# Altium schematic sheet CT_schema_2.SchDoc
size 551 x 486 mm
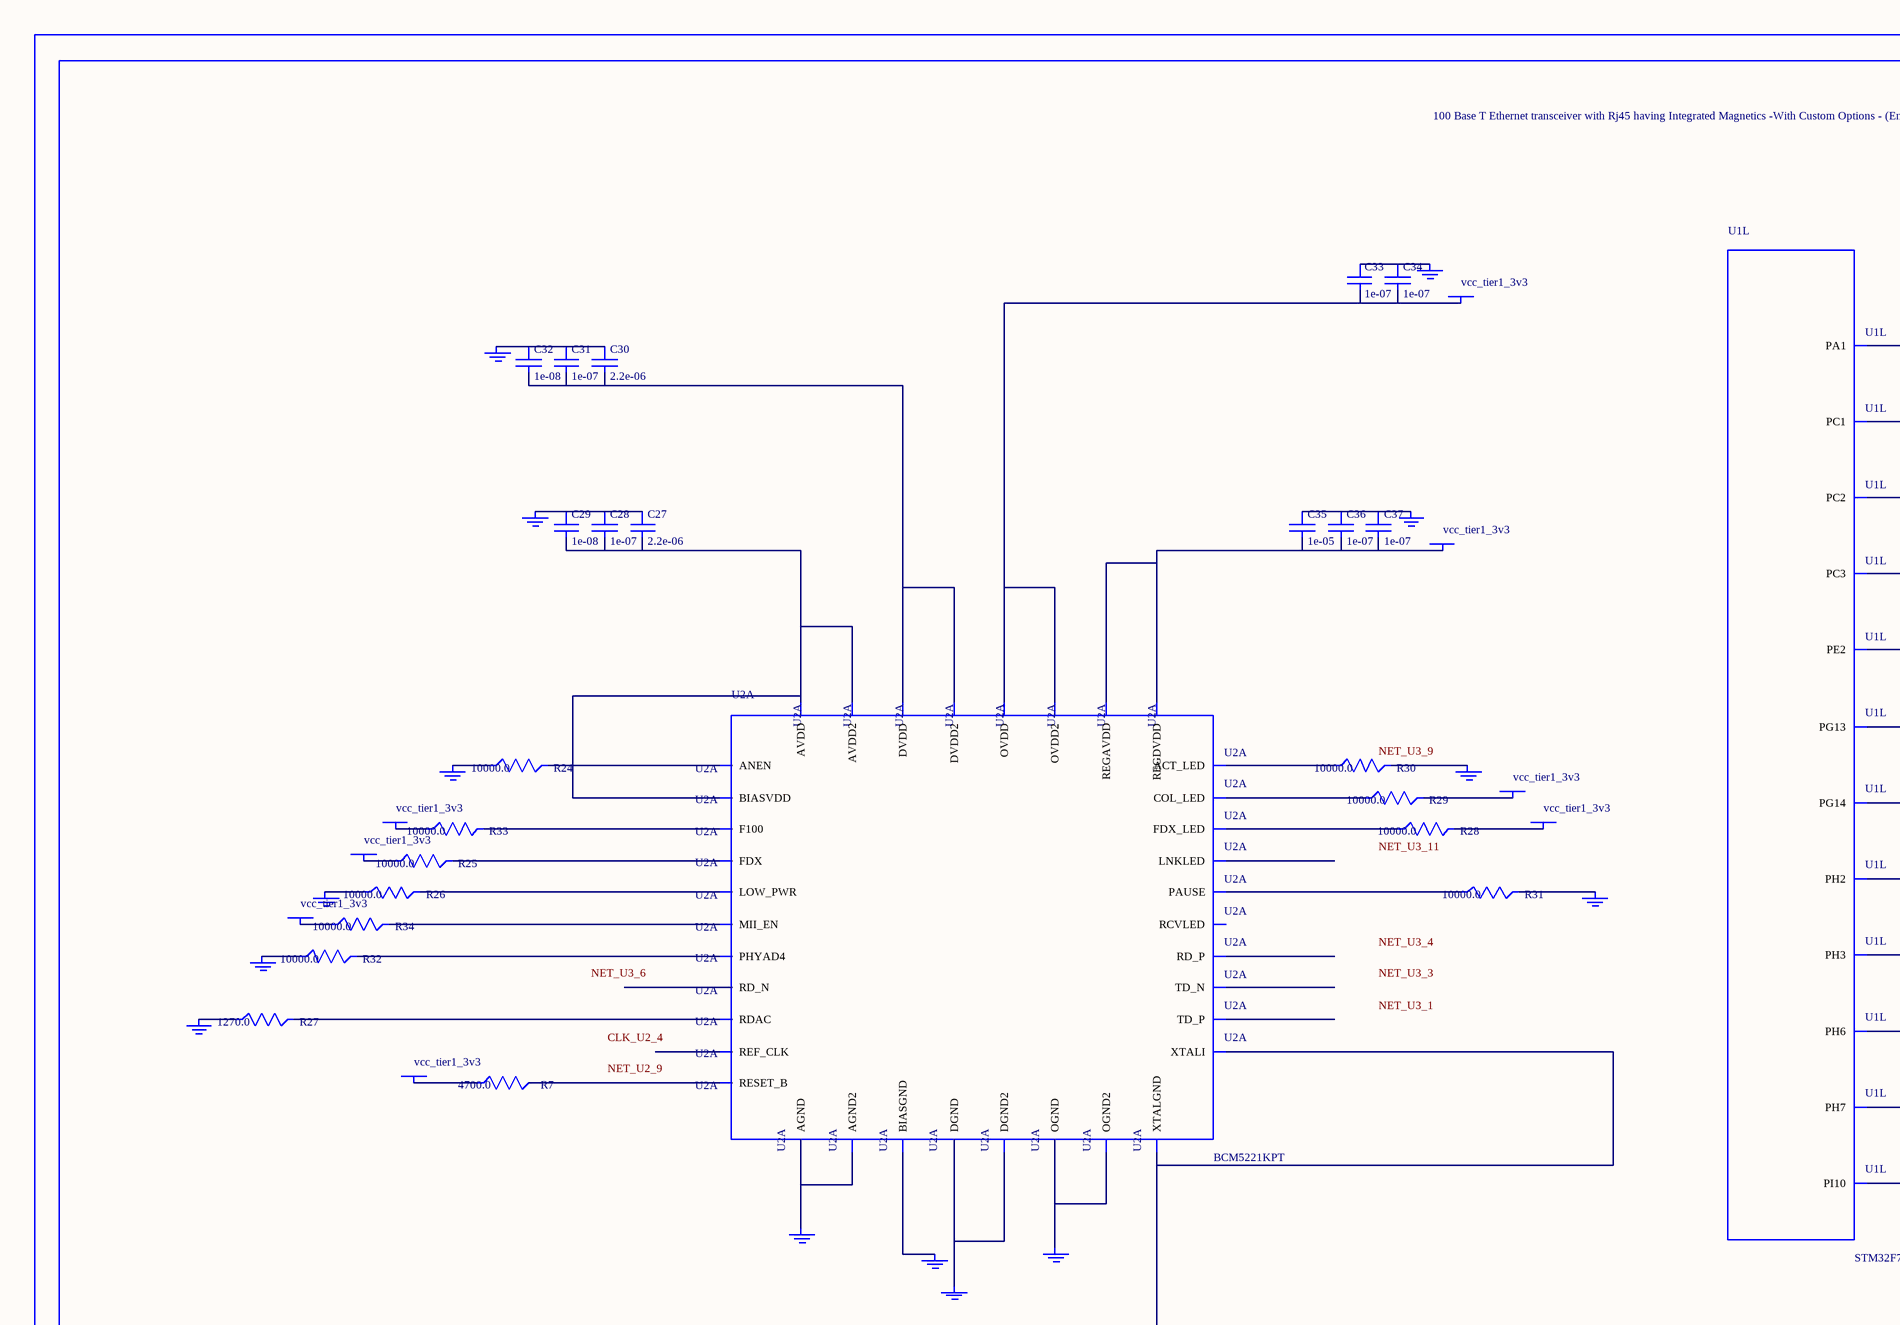
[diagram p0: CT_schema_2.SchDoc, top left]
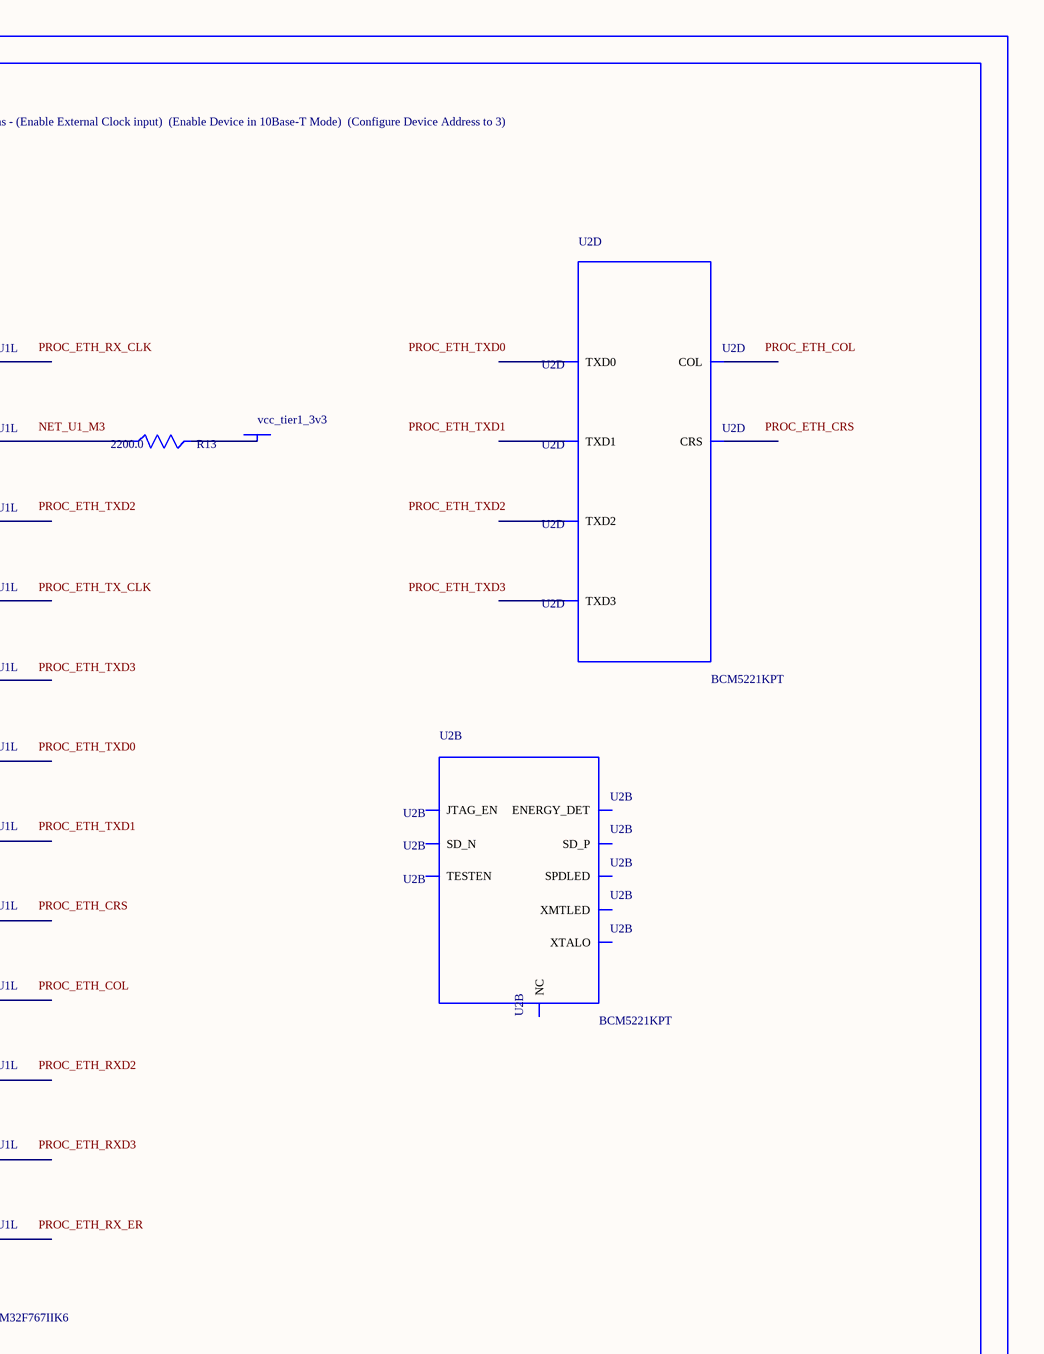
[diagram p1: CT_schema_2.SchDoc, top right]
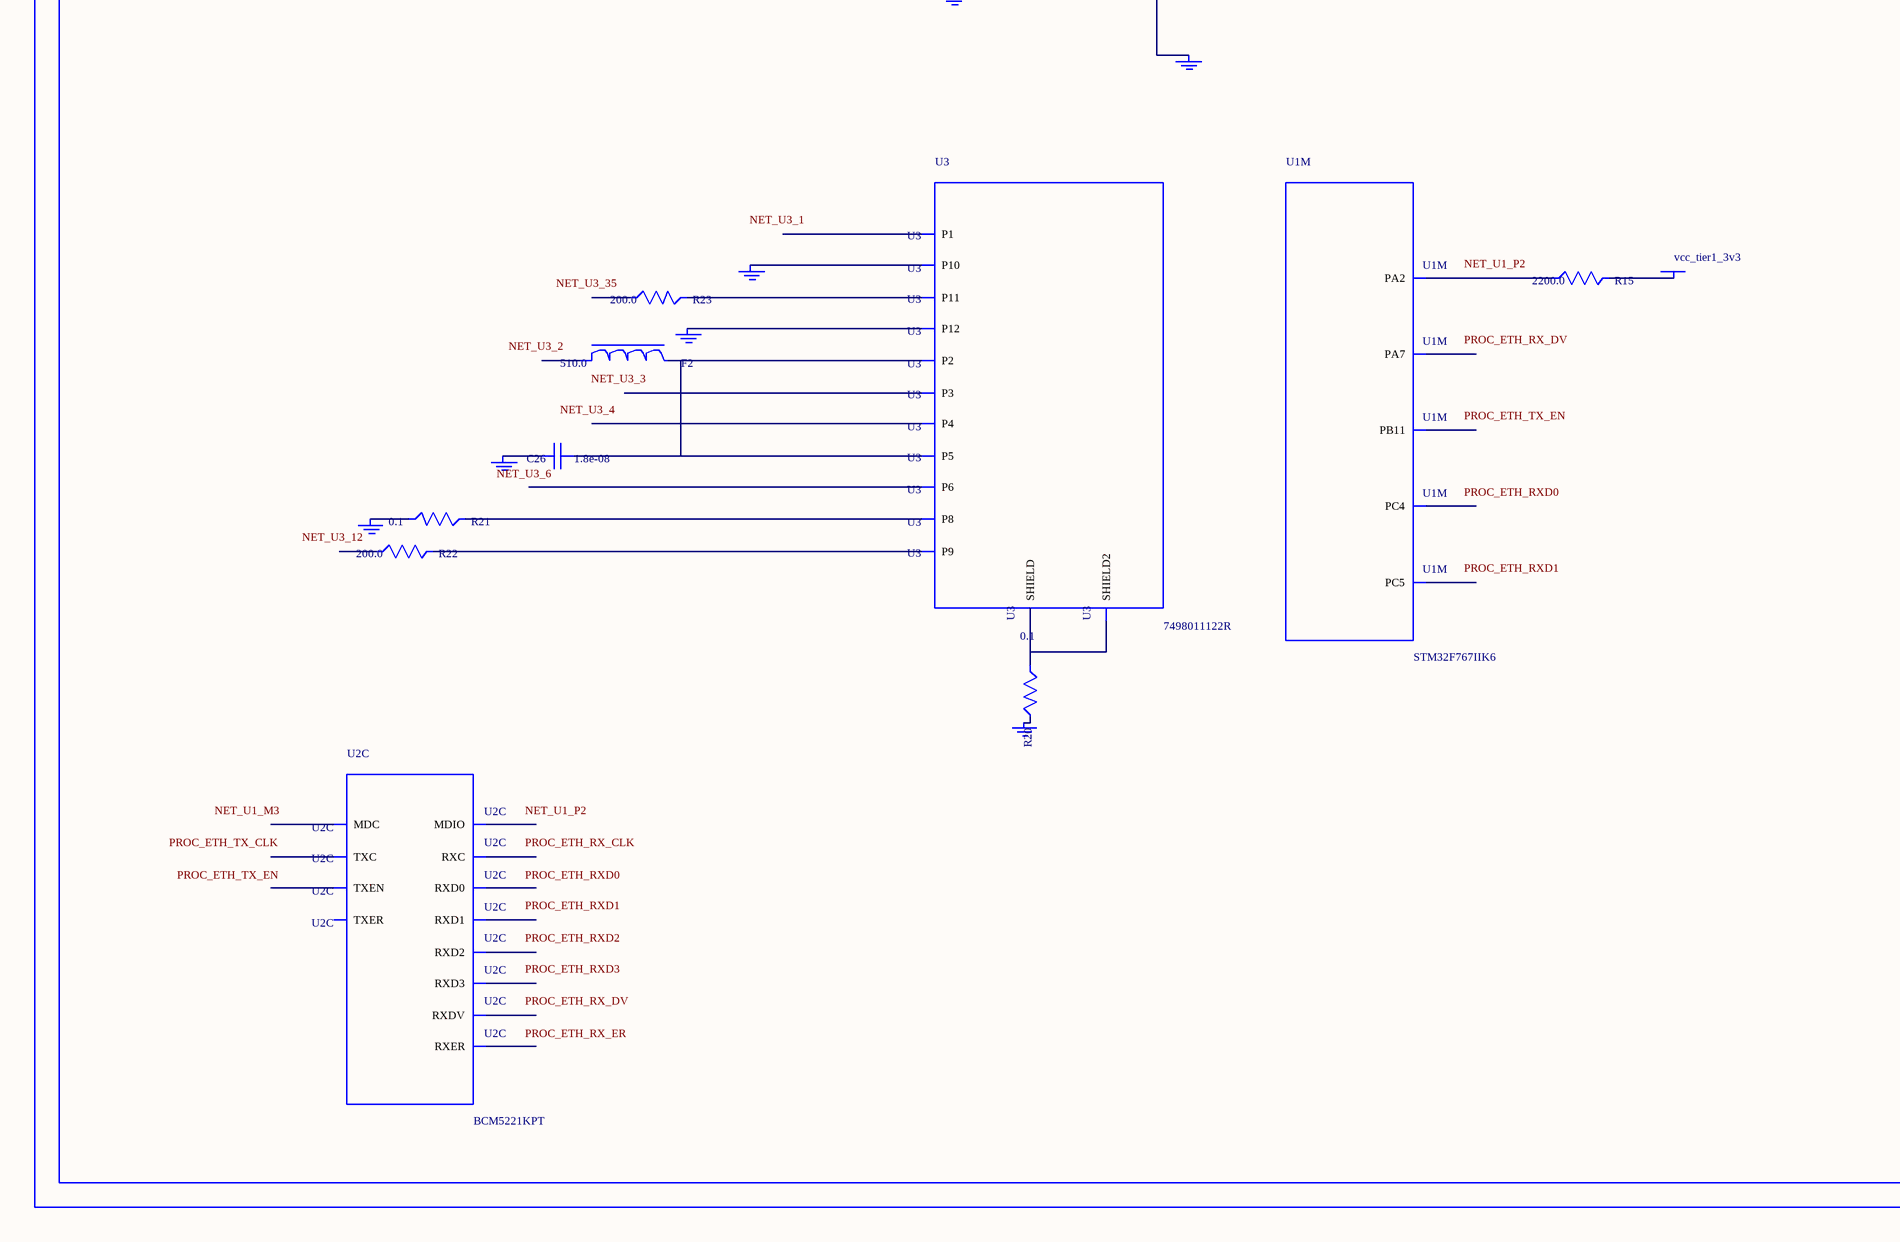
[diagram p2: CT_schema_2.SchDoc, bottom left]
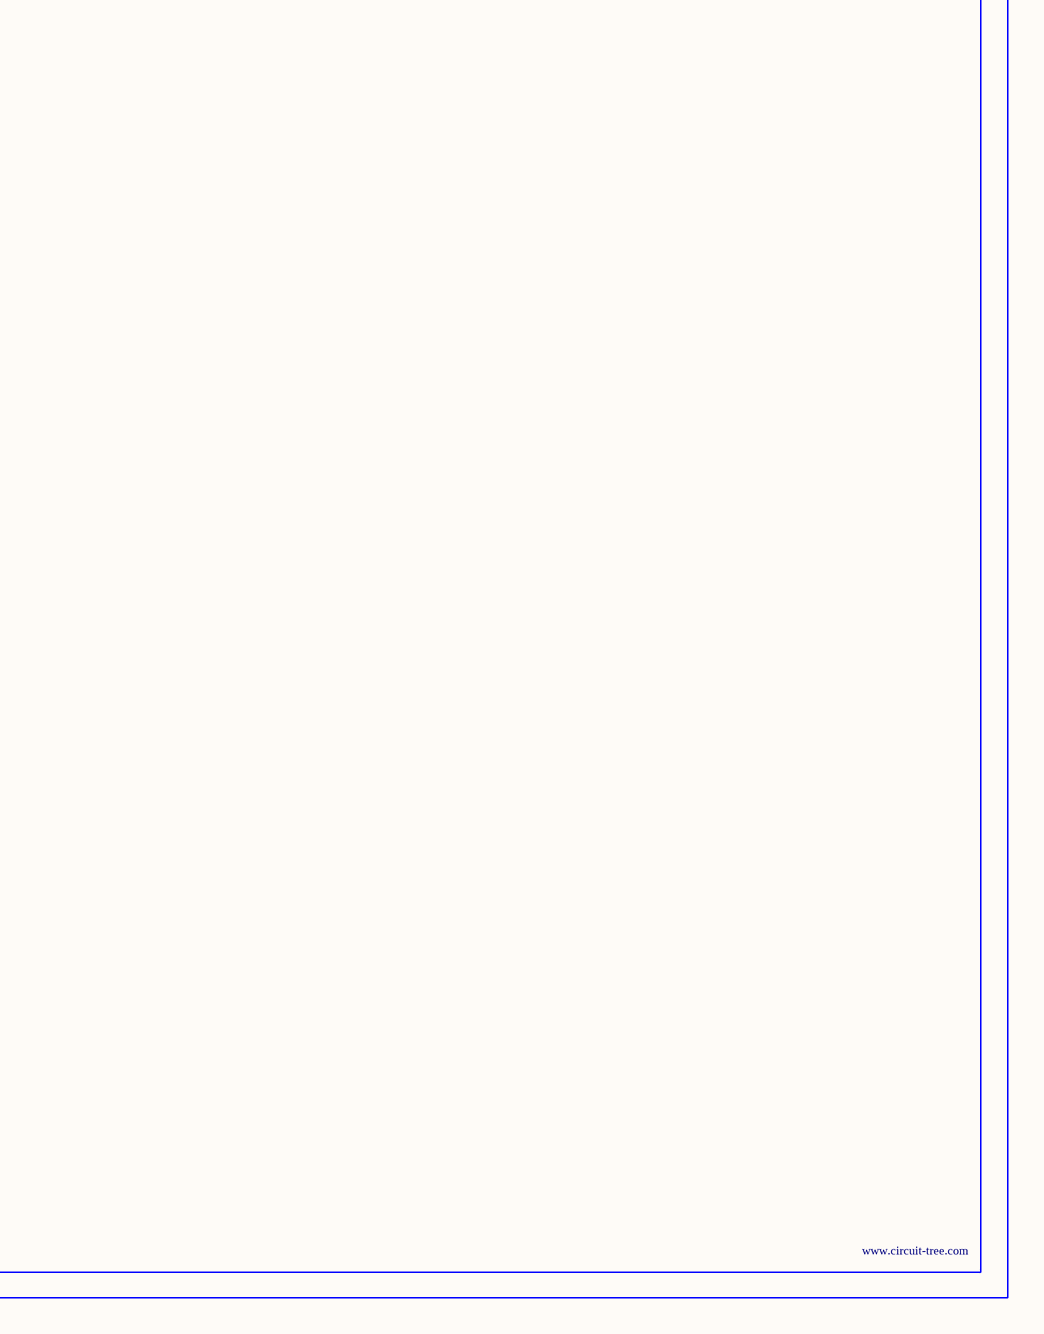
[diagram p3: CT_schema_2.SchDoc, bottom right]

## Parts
BORDER1  (no value)
C26  1.8e-08  [C0402]
C27  2.2e-06  [C0603]
C28  1e-07  [C0402]
C29  1e-08  [C0402]
C30  2.2e-06  [C0603]
C31  1e-07  [C0402]
C32  1e-08  [C0402]
C33  1e-07  [C0402]
C34  1e-07  [C0402]
C35  1e-05  [C0805]
C36  1e-07  [C0402]
C37  1e-07  [C0402]
F2  510.0  [L0603]
GND_INSTANCE_1_0  (no value)
GND_INSTANCE_1_1  (no value)
GND_INSTANCE_1_2  (no value)
GND_INSTANCE_1_3  (no value)
GND_INSTANCE_1_4  (no value)
GND_INSTANCE_1_5  (no value)
GND_INSTANCE_1_6  (no value)
GND_INSTANCE_1_7  (no value)
GND_INSTANCE_1_8  (no value)
GND_INSTANCE_1_9  (no value)
GND_INSTANCE_1_10  (no value)
GND_INSTANCE_1_11  (no value)
GND_INSTANCE_1_12  (no value)
GND_INSTANCE_1_13  (no value)
GND_INSTANCE_1_14  (no value)
GND_INSTANCE_1_15  (no value)
GND_INSTANCE_1_16  (no value)
GND_INSTANCE_1_17  (no value)
GND_INSTANCE_1_18  (no value)
GND_INSTANCE_1_19  (no value)
POWER_INSTANCE_1_0  vcc_tier1_3v3
POWER_INSTANCE_1_1  vcc_tier1_3v3
POWER_INSTANCE_1_2  vcc_tier1_3v3
POWER_INSTANCE_1_3  vcc_tier1_3v3
POWER_INSTANCE_1_4  vcc_tier1_3v3
POWER_INSTANCE_1_5  vcc_tier1_3v3
POWER_INSTANCE_1_6  vcc_tier1_3v3
POWER_INSTANCE_1_7  vcc_tier1_3v3
POWER_INSTANCE_1_8  vcc_tier1_3v3
POWER_INSTANCE_1_9  vcc_tier1_3v3
R7  4700.0  [R0603]
R13  2200.0  [R0603]
R15  2200.0  [R0603]
R20  0.1  [R0603]
R21  0.1  [R0603]
R22  200.0  [R0603]
R23  200.0  [R0603]
R24  10000.0  [R0603]
R25  10000.0  [R0603]
R26  10000.0  [R0603]
R27  1270.0  [R0603]
R28  10000.0  [R0603]
R29  10000.0  [R0603]
R30  10000.0  [R0603]
R31  10000.0  [R0603]
R32  10000.0  [R0603]
R33  10000.0  [R0603]
R34  10000.0  [R0603]
U1  STM32F767IIK6  [UFBGA176_25]  (parts L,M of 17)
U2  BCM5221KPT  [TQFP64_10X10MC]  (parts A,B,C,D of 4)
U3  7498011122R  [7498011122R]

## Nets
NetC26_1: C26.1 F2.2 U3.2(P2) U3.5(P5)
NetC26_2: C26.2 GND_INSTANCE_1_15.0(GND)
NetC27_1: C27.1 C28.1 C29.1 GND_INSTANCE_1_10.0(GND)
NetC27_2: C27.2 C28.2 C29.2 U2.22(BIASVDD) U2.27(AVDD) U2.28(AVDD2)
NetC30_1: C30.1 C31.1 C32.1 GND_INSTANCE_1_1.0(GND)
NetC30_2: C30.2 C31.2 C32.2 U2.2(DVDD) U2.55(DVDD2)
NetC33_1: C33.1 C34.1 GND_INSTANCE_1_0.0(GND)
NetC33_2: C33.2 C34.2 POWER_INSTANCE_1_0.0(PWR) U2.1(OVDD) U2.46(OVDD2)
NetC35_1: C35.1 C36.1 C37.1 GND_INSTANCE_1_2.0(GND)
NetC35_2: C35.2 C36.2 C37.2 POWER_INSTANCE_1_1.0(PWR) U2.3(REGDVDD) U2.20(REGAVDD)
NetGND_INSTANCE_1_3_0: GND_INSTANCE_1_3.0(GND) U2.6(XTALI) U2.7(XTALGND)
NetGND_INSTANCE_1_4_0: GND_INSTANCE_1_4.0(GND) R30.2
NetGND_INSTANCE_1_5_0: GND_INSTANCE_1_5.0(GND) R31.2
NetGND_INSTANCE_1_6_0: GND_INSTANCE_1_6.0(GND) R32.1
NetGND_INSTANCE_1_7_0: GND_INSTANCE_1_7.0(GND) R26.1
NetGND_INSTANCE_1_8_0: GND_INSTANCE_1_8.0(GND) R27.1
NetGND_INSTANCE_1_9_0: GND_INSTANCE_1_9.0(GND) U2.24(BIASGND)
NetGND_INSTANCE_1_11_0: GND_INSTANCE_1_11.0(GND) R24.1
NetGND_INSTANCE_1_12_0: GND_INSTANCE_1_12.0(GND) U2.29(AGND) U2.32(AGND2)
NetGND_INSTANCE_1_13_0: GND_INSTANCE_1_13.0(GND) U2.40(OGND) U2.45(OGND2)
NetGND_INSTANCE_1_14_0: GND_INSTANCE_1_14.0(GND) U2.54(DGND) U2.63(DGND2)
NetGND_INSTANCE_1_16_0: GND_INSTANCE_1_16.0(GND) R21.1
NetGND_INSTANCE_1_17_0: GND_INSTANCE_1_17.0(GND) U3.10(P10)
NetGND_INSTANCE_1_18_0: GND_INSTANCE_1_18.0(GND) U3.12(P12)
NetGND_INSTANCE_1_19_0: GND_INSTANCE_1_19.0(GND) R20.2
NetPOWER_INSTANCE_1_2_0: POWER_INSTANCE_1_2.0(PWR) R28.2
NetPOWER_INSTANCE_1_3_0: POWER_INSTANCE_1_3.0(PWR) R29.2
NetPOWER_INSTANCE_1_4_0: POWER_INSTANCE_1_4.0(PWR) R34.1
NetPOWER_INSTANCE_1_5_0: POWER_INSTANCE_1_5.0(PWR) R33.1
NetPOWER_INSTANCE_1_6_0: POWER_INSTANCE_1_6.0(PWR) R25.1
NetPOWER_INSTANCE_1_7_0: POWER_INSTANCE_1_7.0(PWR) R7.1
NetPOWER_INSTANCE_1_8_0: POWER_INSTANCE_1_8.0(PWR) R13.2
NetPOWER_INSTANCE_1_9_0: POWER_INSTANCE_1_9.0(PWR) R15.2
NetR7_2: R7.2 U2.9(RESET_B)
NetR13_1: R13.1 U1.M3(PC1)
NetR15_1: R15.1 U1.P2(PA2)
NetR20_1: R20.1 U3.13(SHIELD) U3.14(SHIELD2)
NetR21_2: R21.2 U3.8(P8)
NetR22_2: R22.2 U3.9(P9)
NetR23_2: R23.2 U3.11(P11)
NetR24_2: R24.2 U2.38(ANEN)
NetR25_2: R25.2 U2.39(FDX)
NetR26_2: R26.2 U2.16(LOW_PWR)
NetR27_2: R27.2 U2.23(RDAC)
NetR28_1: R28.1 U2.10(FDX_LED)
NetR29_1: R29.1 U2.11(COL_LED)
NetR30_1: R30.1 U2.12(ACT_LED)
NetR31_1: R31.1 U2.13(PAUSE)
NetR32_2: R32.2 U2.14(PHYAD4)
NetR33_2: R33.2 U2.37(F100)
NetR34_2: R34.2 U2.18(MII_EN)

Not connected (* = marked no-connect by the designer): F2 1; R22 1; R23 1; U1 A2(PE2) A7(PG14) A8(PG13) E3(PI10) F4(PH2) G4(PH3) M4(PC2) M5(PC3) M11(PH6) N2(PA1) N5(PC4) N12(PH7) P5(PC5) R3(PA7) R13(PB11); U2 4(REF_CLK) 5(XTALO) 8(NC) 15(TESTEN) 17(ENERGY_DET) 19(SD_N) 21(SD_P) 25(RD_N) 26(RD_P) 30(TD_N) 31(TD_P) 33(RCVLED) 34(XMTLED) 35(LNKLED) 36(SPDLED) 41(MDIO) 42(MDC) 43(RXD3) 44(RXD2) 47(RXD1) 48(RXD0) 49(RXDV) 50(RXC) 51(RXER) 52(TXER) 53(TXC) 56(TXEN) 57(TXD0) 58(TXD1) 59(TXD2) 60(TXD3) 61(COL) 62(CRS) 64(JTAG_EN); U3 1(P1) 3(P3) 4(P4) 6(P6)

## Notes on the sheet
- Labels drawn without touching a wire or pin: CLK_U2_4, NET_U1_M3, NET_U1_P2, NET_U2_9, NET_U3_1, NET_U3_2, NET_U3_3, NET_U3_4, NET_U3_6, NET_U3_9, NET_U3_11, NET_U3_12, NET_U3_35, PROC_ETH_COL, PROC_ETH_CRS, PROC_ETH_RX_CLK, PROC_ETH_RX_DV, PROC_ETH_RX_ER, PROC_ETH_RXD0, PROC_ETH_RXD1, PROC_ETH_RXD2, PROC_ETH_RXD3, PROC_ETH_TX_CLK, PROC_ETH_TX_EN, PROC_ETH_TXD0, PROC_ETH_TXD1, PROC_ETH_TXD2, PROC_ETH_TXD3

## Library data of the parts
BORDER1 = BORDER_PAGE1
C26 = C0402C183K3RAC
C27 C30 = C0603C225K8RACTU
C28 C31 C33 C34 C36 C37 = C0402C104K3RACTU
C29 C32 = C0402C103K3RAC
C35 = C0805C106K8RACTU
F2 = ERA3APB511V
GND_INSTANCE_1_0-GND_INSTANCE_1_19 = GND
POWER_INSTANCE_1_0-POWER_INSTANCE_1_9 = PWR
R7 = RC0603JR-074K7L
R13 R15 = RC0603JR-072K2L
R20 R21 = ERJ-3RSFR10V
R22 R23 = RC0603JR-07200RL
R24-R26 R28-R34 = RC0603JR-0710KL
R27 = RC0603FR-071K27L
